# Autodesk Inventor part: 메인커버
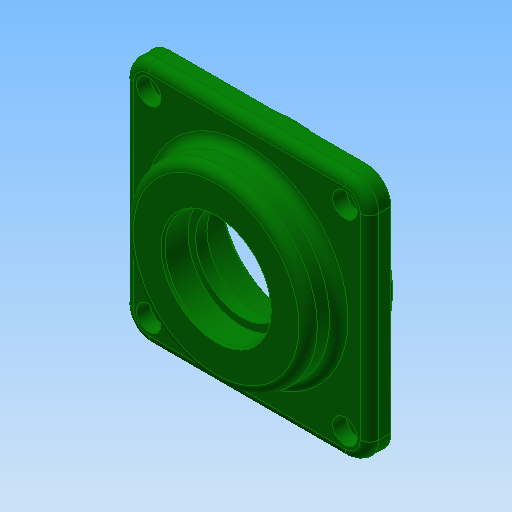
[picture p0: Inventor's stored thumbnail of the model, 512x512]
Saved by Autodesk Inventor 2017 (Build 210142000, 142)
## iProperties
Created: 2018-09
Part Number: 메인커버
Material: 알루미늄 6061
Document SubType Name: Modeling
Designer: mduedu
Density: 2.71 g/cm^3
Mass: 178.493 g
Surface Area: 197.445 cm^2
Volume: 65.8646 cm^3
Appearance: 진녹색
Author: mduedu
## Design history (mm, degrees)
sketch "스케치1"
  geometry: L1 (-40, -40)-(40, -40); L2 (40, -40)-(40, 40); L3 (40, 40)-(-40, 40); L4 (-40, 40)-(-40, -40); L5 (-40, -40)-(40, 40); L6 (40, -40)-(-40, 40); 1 further point
  constraints: 12 end point, 2 midpoint, 2 parallel, 1 horizontal, 1 perpendicular
  dimensions: "d0" = 80 distance of L3.end L2.end; "d1" = 80 distance of L2.end L1.end
extrude "돌출1" new body sketch "스케치1" distance "d2" = 7; taper "d3" = 0 deg
sketch "스케치2"
  geometry: C1 r 30 at (0, 0); 1 further point
  constraints: 1 centre point, 1 coincident
  dimensions: "d4" = 60 diameter of C1
extrude "돌출2" join sketch "스케치2" distance "d5" = 10; taper "d6" = 0 deg
sketch "스케치3"
  geometry: C1 r 32.5 at (0, 0); 1 further point
  constraints: 1 centre point, 1 coincident
  dimensions: "d7" = 65 diameter of C1
extrude "돌출3" join sketch "스케치3" distance "d8" = 9; taper "d9" = 0 deg
sketch "스케치4"
  geometry: L1 (-32.5, -9)-(32.5, -9) reference; L2 (30, 17)-(-30, 17) reference; L3 (0, 17)-(0, -9); L4 (0, -9)-(23.5, -9); L5 (23.5, -9)-(23.5, 5); L6 (23.5, 5)-(0, 5); L7 (0, 5)-(0, -9); L8 (0, 5)-(15, 5); L9 (15, 5)-(15, 8.7); L10 (15, 8.7)-(0, 8.7); L11 (0, 8.7)-(0, 5); L12 (0, 8.7)-(17.5, 8.7); L13 (17.5, 8.7)-(17.5, 17); L14 (17.5, 17)-(0, 17); L15 (0, 17)-(0, 8.7); 1 further point
  constraints: 26 end point, 6 parallel, 3 horizontal, 3 perpendicular, 2 midpoint, 1 point on line
  dimensions: "d10" = 14 distance of L4.end L5.end; "d12" = 8.3 distance of L12.end L13.end; "d13" = 35 diameter of L13 L3; "d14" = 30 diameter of L9 L3; "d15" = 47 diameter of L5 L3
revolve "회전1" sketch "스케치4" stored, may be unused: angle "d16" = 90 deg
fillet "모깎기1" dims "d17" = 8
fillet "모깎기2" dims "d18" = 3
fillet "모깎기3" dims "d19" = 3
chamfer "모따기1" distance "d20" = 0.8; stored, may be unused: second distance "d21" = 2, angle "d22" = 30 deg
chamfer "모따기2" distance "d23" = 1; stored, may be unused: second distance "d24" = 2, angle "d25" = 30 deg
fillet "모깎기4" dims "d26" = 0.3
sketch "스케치5"
  geometry: A1 r 8 centre (-32, 32) between (-32, 40) and (-40, 32) reference; A2 r 8 centre (-32, -32) between (-40, -32) and (-32, -40) reference; A3 r 8 centre (32, -32) between (32, -40) and (40, -32) reference; A4 r 8 centre (32, 32) between (40, 32) and (32, 40) reference; 5 further points
  constraints: 4 coincident
hole "구멍1" sketch "스케치5" at (-32, 32), (32, 32), (32, -32), (-32, -32) diameter "d27" = 4.5; stored, may be unused: countersink angle "d31" = 90 deg, drill point angle "d33" = 118 deg; dims "d28" = 6, "d29" = 8, "d30" = 4.4, "d32" = 8
fillet "모깎기5" dims "d34" = 0.5
node "솔리드1"
